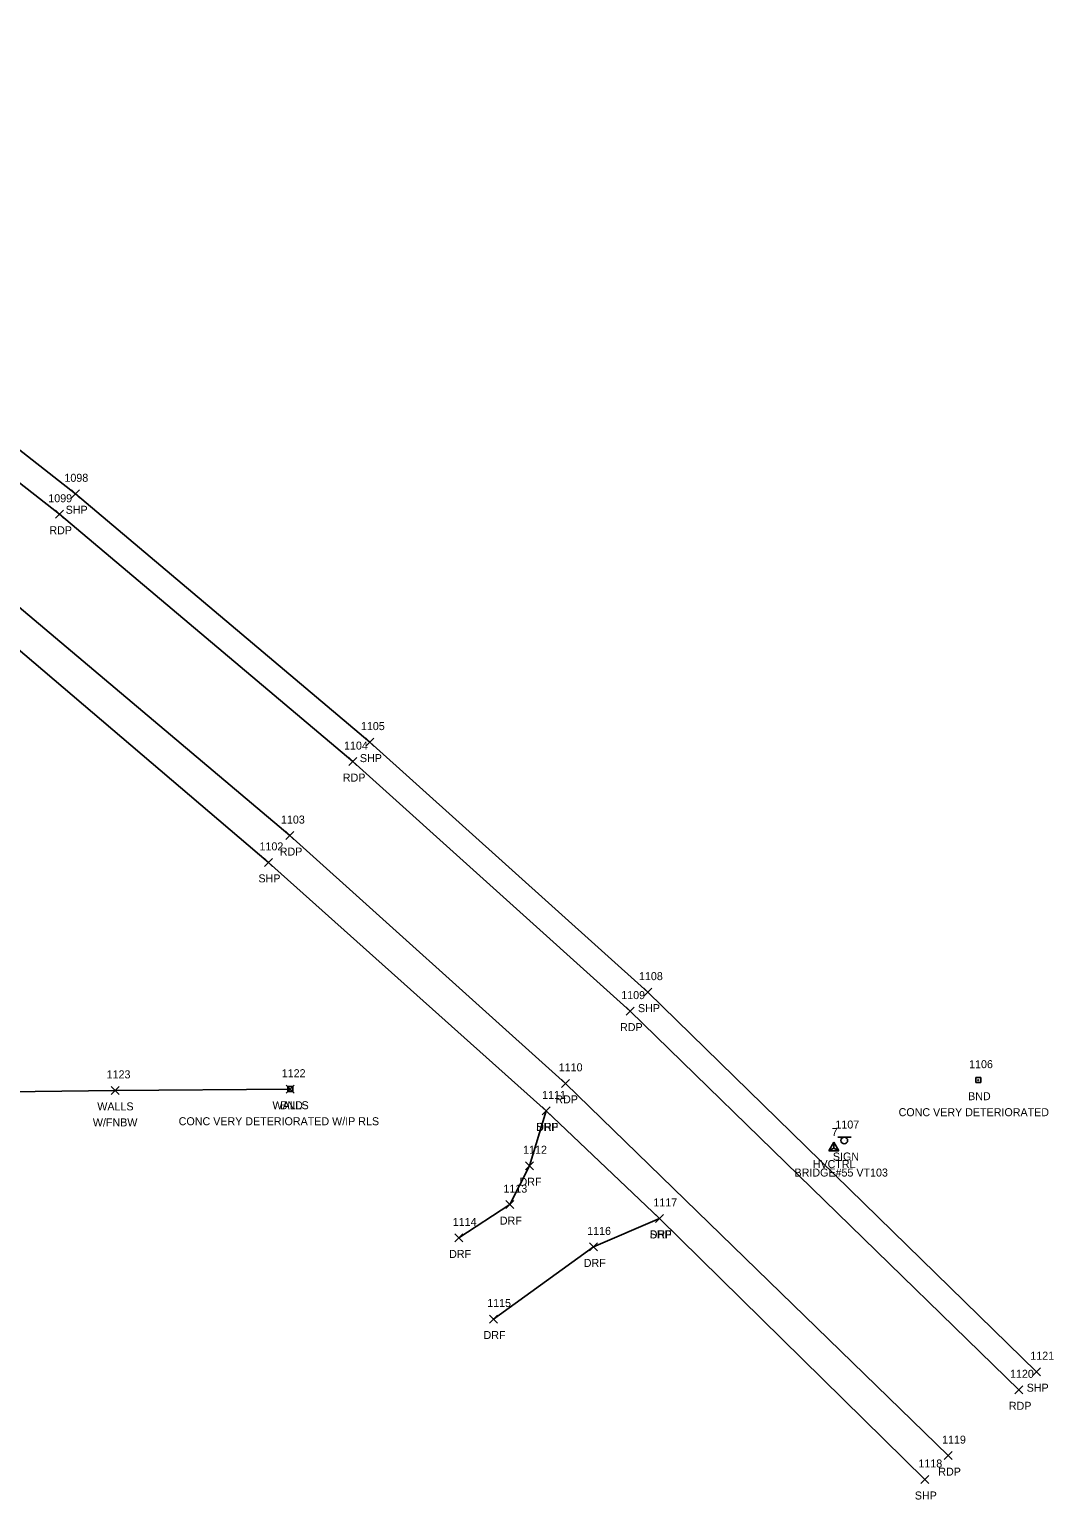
# Model space of a CAD drawing. Extents: x 1519347 to 1522636, y 378779 to 379832.
# Drawn here: x 1522380.1 to 1522636.1, y 378808.2 to 379175.6 of the extents above; entities that cross this region are included whole.
import ezdxf

# ---------------------------------------------------------------- set-up
doc = ezdxf.new("R2010")
doc.units = 0
for name, color, linetype in [('C_A', 7, 'Continuous'), ('C_I', 7, 'Continuous'), ('CPSM', 7, 'Continuous'), ('L_A', 7, 'Continuous'), ('L_C', 7, 'Continuous'), ('L_I', 7, 'Continuous'), ('L_TIC', 7, 'Continuous'), ('LWS', 7, 'Continuous'), ('M_A', 7, 'Continuous'), ('M_C', 7, 'Continuous'), ('M_I', 7, 'Continuous'), ('MHBP', 7, 'Continuous'), ('P_A', 7, 'Continuous'), ('P_I', 7, 'Continuous'), ('P_TIC', 7, 'Continuous'), ('PE', 7, 'Continuous'), ('PSP', 7, 'Continuous'), ('R_A', 7, 'Continuous'), ('R_I', 7, 'Continuous'), ('R_TIC', 7, 'Continuous'), ('RDF', 7, 'Continuous'), ('S_A', 7, 'Continuous'), ('S_C', 7, 'Continuous'), ('S_I', 7, 'Continuous'), ('SSGN', 7, 'Continuous')]:
    doc.layers.add(name, color=color, linetype=linetype)

msp = doc.modelspace()

# ---------------------------------------------------------------- linework, layer by layer
at = {"layer": 'CPSM'}
for p, q in [((1522579.95, 378895.29), (1522581.2, 378897.46)), ((1522579.95, 378895.29), (1522581.2, 378896.01)), ((1522579.95, 378895.29), (1522582.45, 378895.29)), ((1522582.45, 378895.29), (1522581.2, 378897.46)), ((1522581.2, 378896.01), (1522581.2, 378897.46)), ((1522581.2, 378896.01), (1522581.2, 378896.01)), ((1522581.2, 378896.01), (1522582.45, 378895.29))]:
    msp.add_line(p, q, dxfattribs=at)
at = {"layer": 'L_TIC'}
for points in [[(1522400.54, 378909.43), (1522402.54, 378911.43)], [(1522402.54, 378909.43), (1522400.54, 378911.43)], [(1522444.31, 378909.72), (1522446.31, 378911.72)], [(1522446.31, 378909.72), (1522444.31, 378911.72)]]:
    msp.add_lwpolyline(points, dxfattribs=at)
at = {"layer": 'LWS'}
msp.add_lwpolyline([(1522445.31, 378910.72), (1522401.54, 378910.43), (1522348.21, 378909.74), (1522295.88, 378908.39), (1522245.08, 378908.42), (1522202.2, 378906.68), (1522157.16, 378906.96), (1522120.07, 378904.84), (1522091.12, 378905.13), (1522034.79, 378905.64), (1521976.72, 378902.28), (1521929.9, 378901.52), (1521875.34, 378901.77), (1521835.92, 378899.64), (1521789.94, 378904.13), (1521732.75, 378904.41), (1521692.11, 378903.65), (1521648.67, 378903.93), (1521616.94, 378904.79), (1521567.34, 378904.32)], dxfattribs=at)
at = {"layer": 'MHBP'}
for p, q in [((1522617.88, 378913.64), (1522616.63, 378913.64)), ((1522616.63, 378913.64), (1522616.63, 378912.39)), ((1522617.88, 378913.64), (1522616.63, 378913.64)), ((1522616.63, 378913.64), (1522616.63, 378912.39)), ((1522616.63, 378912.39), (1522617.88, 378912.39)), ((1522616.63, 378912.39), (1522617.88, 378912.39)), ((1522617.88, 378912.39), (1522617.88, 378913.64)), ((1522617.88, 378912.39), (1522617.88, 378913.64)), ((1522445.96, 378911.38), (1522444.71, 378911.38)), ((1522444.71, 378911.38), (1522444.71, 378910.13)), ((1522445.96, 378911.38), (1522444.71, 378911.38)), ((1522444.71, 378911.38), (1522444.71, 378910.13)), ((1522444.71, 378910.13), (1522445.96, 378910.13)), ((1522444.71, 378910.13), (1522445.96, 378910.13)), ((1522445.96, 378910.13), (1522445.96, 378911.38)), ((1522445.96, 378910.13), (1522445.96, 378911.38))]:
    msp.add_line(p, q, dxfattribs=at)
for centre in [(1522617.23, 378912.97), (1522445.31, 378910.71)]:
    msp.add_circle(centre, 0.0833, dxfattribs=at)
at = {"layer": 'P_TIC'}
for points in [[(1522390.65, 379058.53), (1522392.65, 379060.53)], [(1522392.65, 379058.53), (1522390.65, 379060.53)], [(1522386.62, 379053.41), (1522388.62, 379055.41)], [(1522388.62, 379053.41), (1522386.62, 379055.41)], [(1522464.18, 378996.47), (1522466.18, 378998.47)], [(1522466.18, 378996.47), (1522464.18, 378998.47)], [(1522459.96, 378991.6), (1522461.96, 378993.6)], [(1522461.96, 378991.6), (1522459.96, 378993.6)], [(1522444.19, 378973.11), (1522446.19, 378975.11)], [(1522446.19, 378973.11), (1522444.19, 378975.11)], [(1522438.83, 378966.41), (1522440.83, 378968.41)], [(1522440.83, 378966.41), (1522438.83, 378968.41)], [(1522533.68, 378933.98), (1522535.68, 378935.98)], [(1522535.68, 378933.98), (1522533.68, 378935.98)], [(1522529.24, 378929.24), (1522531.24, 378931.24)], [(1522531.24, 378929.24), (1522529.24, 378931.24)], [(1522513.07, 378911.19), (1522515.07, 378913.19)], [(1522515.07, 378911.19), (1522513.07, 378913.19)], [(1522508.25, 378904.3), (1522510.25, 378906.3)], [(1522510.25, 378904.3), (1522508.25, 378906.3)], [(1522536.61, 378877.43), (1522538.61, 378879.43)], [(1522538.61, 378877.43), (1522536.61, 378879.43)], [(1522630.83, 378839.12), (1522632.83, 378841.12)], [(1522632.83, 378839.12), (1522630.83, 378841.12)], [(1522626.42, 378834.6), (1522628.42, 378836.6)], [(1522628.42, 378834.6), (1522626.42, 378836.6)], [(1522608.78, 378818.15), (1522610.78, 378820.15)], [(1522610.78, 378818.15), (1522608.78, 378820.15)], [(1522602.87, 378812.19), (1522604.87, 378814.19)], [(1522604.87, 378812.19), (1522602.87, 378814.19)]]:
    msp.add_lwpolyline(points, dxfattribs=at)
at = {"layer": 'PE'}
for points in [[(1521529.39, 379535.32), (1521632.62, 379496.8), (1521722.31, 379458.96), (1521816.06, 379415.75), (1521903.5, 379372.19), (1521985.15, 379327.91), (1522068.34, 379279.51), (1522152.8, 379226.58), (1522231.81, 379172.75), (1522311.43, 379114.1), (1522387.62, 379054.41), (1522460.96, 378992.6), (1522530.24, 378930.24), (1522627.42, 378835.6)], [(1521521.96, 379512.45), (1521622.97, 379474.43), (1521713.3, 379436.47), (1521805.17, 379393.75), (1521891.16, 379351.25), (1521973.22, 379306.84), (1522055.83, 379258.59), (1522137.28, 379207.8), (1522217.99, 379153.03), (1522296.46, 379094.97), (1522371.63, 379036.1), (1522445.19, 378974.11), (1522514.07, 378912.19), (1522609.78, 378819.15)]]:
    msp.add_lwpolyline(points, dxfattribs=at)
at = {"layer": 'PSP'}
for points in [[(1521531.82, 379542.79), (1521635.1, 379503.97), (1521725.46, 379466.08), (1521819.09, 379422.88), (1521907.05, 379378.96), (1521988.73, 379335.06), (1522072.92, 379286.87), (1522157.1, 379232.77), (1522235.26, 379178.41), (1522315.3, 379119.36), (1522391.65, 379059.53), (1522465.18, 378997.47), (1522534.68, 378934.98), (1522631.83, 378840.12)], [(1521519.02, 379505.15), (1521619.86, 379467.25), (1521710.1, 379429.27), (1521802.41, 379386.84), (1521887.29, 379344.47), (1521969.86, 379299.81), (1522051.39, 379251.77), (1522132.8, 379200.77), (1522213.2, 379146), (1522291.37, 379088.51), (1522366.45, 379029.85), (1522439.83, 378967.41), (1522509.25, 378905.3), (1522537.61, 378878.43), (1522603.87, 378813.19)]]:
    msp.add_lwpolyline(points, dxfattribs=at)
at = {"layer": 'R_TIC'}
for points in [[(1522508.25, 378904.3), (1522510.25, 378906.3)], [(1522510.25, 378904.3), (1522508.25, 378906.3)], [(1522504.07, 378890.6), (1522506.07, 378892.6)], [(1522506.07, 378890.6), (1522504.07, 378892.6)], [(1522499.15, 378880.88), (1522501.15, 378882.88)], [(1522501.15, 378880.88), (1522499.15, 378882.88)], [(1522536.61, 378877.43), (1522538.61, 378879.43)], [(1522538.61, 378877.43), (1522536.61, 378879.43)], [(1522486.48, 378872.55), (1522488.48, 378874.55)], [(1522488.48, 378872.55), (1522486.48, 378874.55)], [(1522520.13, 378870.31), (1522522.13, 378872.31)], [(1522522.13, 378870.31), (1522520.13, 378872.31)], [(1522495.09, 378852.29), (1522497.09, 378854.29)], [(1522497.09, 378852.29), (1522495.09, 378854.29)]]:
    msp.add_lwpolyline(points, dxfattribs=at)
at = {"layer": 'RDF'}
for points in [[(1522509.25, 378905.3), (1522505.07, 378891.6), (1522500.15, 378881.88), (1522487.48, 378873.55)], [(1522496.09, 378853.29), (1522521.13, 378871.31), (1522537.61, 378878.43)]]:
    msp.add_lwpolyline(points, dxfattribs=at)
at = {"layer": 'SSGN'}
for p, q in [((1522582.14, 378898.75), (1522585.47, 378898.75)), ((1522583.78, 378897.92), (1522583.78, 378897.92))]:
    msp.add_line(p, q, dxfattribs=at)
msp.add_circle((1522583.78, 378897.92), 0.833, dxfattribs=at)

# ---------------------------------------------------------------- texts
at = {"layer": 'C_A'}
msp.add_text('HVCTRL', height=2, dxfattribs=at).set_placement((1522575.89, 378891.01))
at = {"layer": 'C_I'}
msp.add_text('7', height=2, dxfattribs=at).set_placement((1522580.63, 378899.01))
at = {"layer": 'L_A'}
for p in [(1522397.08, 378905.43), (1522440.85, 378905.72)]:
    msp.add_text('WALLS', height=2, dxfattribs=at).set_placement(p)
at = {"layer": 'L_C'}
msp.add_text('W/FNBW', height=2, dxfattribs=at).set_placement((1522395.97, 378901.43))
at = {"layer": 'L_I'}
for s, p in [('1123', (1522399.42, 378913.43)), ('1122', (1522443.18, 378913.72))]:
    msp.add_text(s, height=2, dxfattribs=at).set_placement(p)
at = {"layer": 'M_A'}
for p in [(1522614.72, 378907.98), (1522442.79, 378905.72)]:
    msp.add_text('BND', height=2, dxfattribs=at).set_placement(p)
at = {"layer": 'M_C'}
for s, p in [('CONC VERY DETERIORATED', (1522597.35, 378903.98)), ('CONC VERY DETERIORATED W/IP RLS', (1522417.43, 378901.72))]:
    msp.add_text(s, height=2, dxfattribs=at).set_placement(p)
at = {"layer": 'M_I'}
for s, p in [('1106', (1522614.97, 378915.98)), ('1122', (1522443.18, 378913.72))]:
    msp.add_text(s, height=2, dxfattribs=at).set_placement(p)
at = {"layer": 'P_A'}
for s, p in [('SHP', (1522389.18, 379054.53)), ('RDP', (1522385.1, 379049.41)), ('SHP', (1522462.71, 378992.47)), ('RDP', (1522458.45, 378987.6)), ('RDP', (1522442.68, 378969.11)), ('SHP', (1522437.36, 378962.41)), ('SHP', (1522532.21, 378929.98)), ('RDP', (1522527.73, 378925.24)), ('RDP', (1522511.56, 378907.19)), ('SHP', (1522506.79, 378900.3)), ('SHP', (1522535.15, 378873.43)), ('SHP', (1522629.37, 378835.12)), ('RDP', (1522624.91, 378830.6)), ('RDP', (1522607.27, 378814.15)), ('SHP', (1522601.41, 378808.19))]:
    msp.add_text(s, height=2, dxfattribs=at).set_placement(p)
at = {"layer": 'P_I'}
for s, p in [('1098', (1522388.87, 379062.53)), ('1099', (1522384.84, 379057.41)), ('1105', (1522462.97, 379000.47)), ('1104', (1522458.75, 378995.6)), ('1103', (1522442.99, 378977.11)), ('1102', (1522437.62, 378970.41)), ('1108', (1522532.47, 378937.98)), ('1109', (1522528.03, 378933.24)), ('1110', (1522512.42, 378915.19)), ('1111', (1522508.26, 378908.3)), ('1117', (1522536.06, 378881.43)), ('1121', (1522630.27, 378843.12)), ('1120', (1522625.2, 378838.6)), ('1119', (1522608.22, 378822.15)), ('1118', (1522602.31, 378816.19))]:
    msp.add_text(s, height=2, dxfattribs=at).set_placement(p)
at = {"layer": 'R_A'}
for p in [(1522506.79, 378900.3), (1522502.61, 378886.6), (1522497.69, 378876.88), (1522535.15, 378873.43), (1522485.01, 378868.55), (1522518.67, 378866.31), (1522493.62, 378848.29)]:
    msp.add_text('DRF', height=2, dxfattribs=at).set_placement(p)
at = {"layer": 'R_I'}
for s, p in [('1111', (1522508.26, 378908.3)), ('1112', (1522503.51, 378894.6)), ('1113', (1522498.59, 378884.88)), ('1117', (1522536.06, 378881.43)), ('1114', (1522485.92, 378876.55)), ('1116', (1522519.52, 378874.31)), ('1115', (1522494.53, 378856.29))]:
    msp.add_text(s, height=2, dxfattribs=at).set_placement(p)
at = {"layer": 'S_A'}
msp.add_text('SIGN', height=2, dxfattribs=at).set_placement((1522580.92, 378892.9))
at = {"layer": 'S_C'}
msp.add_text('BRIDGE#55 VT103', height=2, dxfattribs=at).set_placement((1522571.34, 378888.9))
at = {"layer": 'S_I'}
msp.add_text('1107', height=2, dxfattribs=at).set_placement((1522581.56, 378900.9))

doc.saveas('drawing.dxf')
